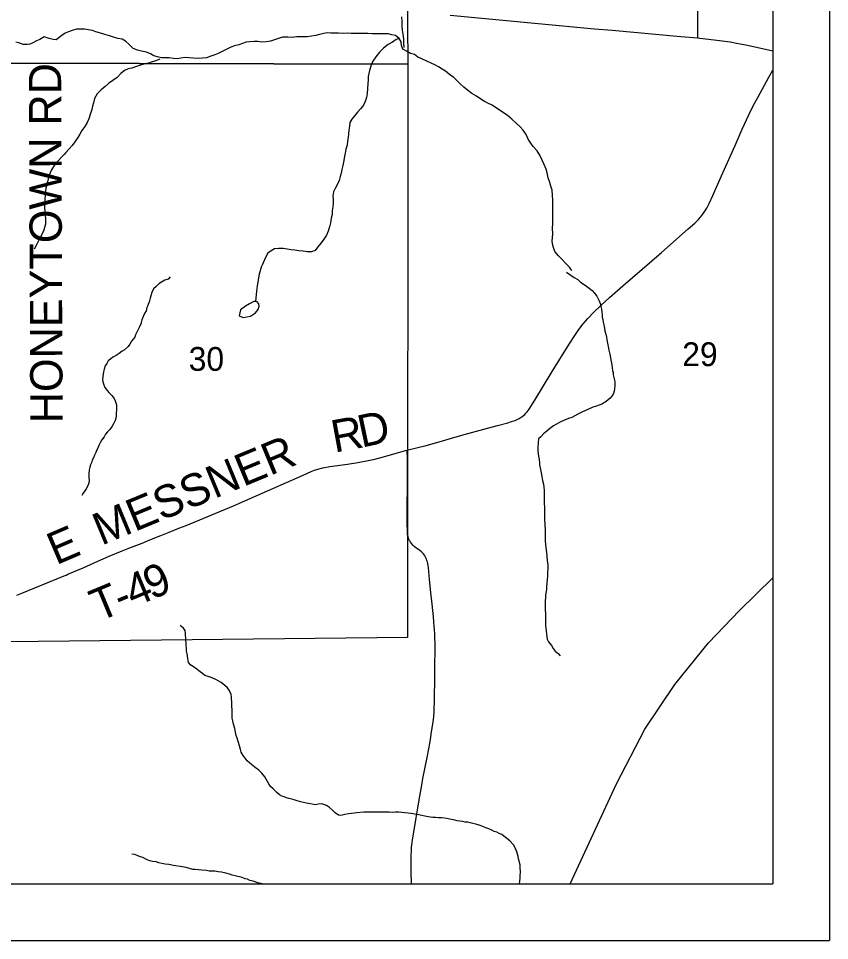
# Model space of a CAD drawing. Extents: x 0 to 34, y 0 to 22.
# Drawn here: x 23.331 to 24.758, y 9.078 to 10.698 of the extents above; entities that cross this region are included whole.
import ezdxf

# ---------------------------------------------------------------- set-up
doc = ezdxf.new("R2010")
doc.units = 0
for name, color, linetype in [('GM_X_County_Road_Text', 7, 'Continuous'), ('GM_X_Minor_Lake', 7, 'Continuous'), ('GM_X_Minor_River', 7, 'Continuous'), ('GM_X_Rail_Line', 7, 'Continuous'), ('GM_X_Section', 7, 'Continuous'), ('GM_X_Section_Text', 7, 'Continuous'), ('GM_X_Township_Road', 7, 'Continuous'), ('GM_X_Township_Road_Text', 7, 'Continuous'), ('GM_X_US_Route', 7, 'Continuous'), ('SH_Data', 7, 'Continuous')]:
    doc.layers.add(name, color=color, linetype=linetype)

msp = doc.modelspace()

# ---------------------------------------------------------------- linework, layer by layer
at = {"layer": 'GM_X_Minor_Lake'}
for points in [[(23.745, 10.2008), (23.7371, 10.197), (23.7303, 10.1927), (23.7216, 10.1862), (23.719, 10.1756), (23.7263, 10.173), (23.7391, 10.1753), (23.7478, 10.1807), (23.7526, 10.1868), (23.7545, 10.1925), (23.7537, 10.1967)], [(23.7537, 10.1967), (23.7511, 10.2002), (23.7491, 10.2011), (23.745, 10.2008)]]:
    msp.add_lwpolyline(points, dxfattribs=at)
at = {"layer": 'GM_X_Minor_River'}
for points in [[(24.0048, 10.7012), (24.0052, 10.6929), (24.0053, 10.6856), (24.0061, 10.678), (24.0073, 10.6708), (24.0085, 10.6628), (24.0086, 10.6552), (24.009, 10.6476)], [(23.407, 10.6682), (23.3973, 10.6611), (23.3917, 10.6615), (23.3852, 10.6633), (23.376, 10.6659), (23.3685, 10.6616), (23.3624, 10.6592), (23.356, 10.6557), (23.3507, 10.6534), (23.3462, 10.6526), (23.3389, 10.6525), (23.3313, 10.6554), (23.3263, 10.6565)], [(23.7109, 10.6505), (23.7045, 10.6478), (23.6976, 10.6447), (23.6905, 10.6409), (23.6825, 10.637), (23.6761, 10.6343), (23.6692, 10.6319), (23.6617, 10.6292), (23.6548, 10.6284), (23.6465, 10.6279), (23.6381, 10.6286), (23.6312, 10.6293), (23.6244, 10.6297), (23.6164, 10.6285), (23.61, 10.6276), (23.6039, 10.628), (23.5963, 10.6291), (23.5898, 10.6294), (23.5826, 10.6293), (23.5753, 10.6312), (23.5692, 10.633), (23.5631, 10.636), (23.5559, 10.639), (23.5475, 10.6408), (23.5406, 10.6427), (23.533, 10.6456), (23.5257, 10.6528), (23.5192, 10.6585), (23.5131, 10.6622), (23.5055, 10.6633), (23.4982, 10.6655), (23.491, 10.6677), (23.4826, 10.6703), (23.4735, 10.6729), (23.467, 10.6748), (23.4609, 10.677), (23.4472, 10.6799), (23.4399, 10.6799), (23.4331, 10.6794), (23.4255, 10.6775), (23.4191, 10.6751), (23.413, 10.6724), (23.407, 10.6682)], [(24.3044, 10.2554), (24.3001, 10.2614), (24.2929, 10.2686), (24.2875, 10.2746), (24.281, 10.2814), (24.2744, 10.2886), (24.2709, 10.2996), (24.2697, 10.3072), (24.2704, 10.3133), (24.2711, 10.3201), (24.2707, 10.33), (24.271, 10.3372), (24.2709, 10.3448), (24.2712, 10.352), (24.2711, 10.3627), (24.2711, 10.3692), (24.271, 10.3783), (24.2705, 10.3878), (24.2697, 10.3965), (24.2677, 10.4034), (24.2658, 10.4098), (24.2631, 10.4181), (24.2611, 10.4269), (24.2591, 10.4337), (24.2552, 10.4428), (24.2518, 10.4508), (24.2479, 10.4583), (24.2433, 10.4655), (24.2367, 10.4731), (24.2321, 10.4795), (24.2279, 10.4863), (24.224, 10.4946), (24.219, 10.5022), (24.2136, 10.5082), (24.2067, 10.5146), (24.1991, 10.5214), (24.1906, 10.5286), (24.1845, 10.5327), (24.1784, 10.5365), (24.1704, 10.5417), (24.1643, 10.5462), (24.1581, 10.5492), (24.1509, 10.5526), (24.1444, 10.5567), (24.1367, 10.5616), (24.1283, 10.5665), (24.1211, 10.5725), (24.1142, 10.5774), (24.108, 10.5838), (24.1019, 10.5895), (24.0965, 10.5955), (24.0897, 10.5996), (24.0824, 10.6057), (24.0763, 10.6094), (24.0698, 10.6135), (24.0637, 10.6169), (24.0568, 10.6199), (24.0492, 10.6236), (24.0408, 10.6274), (24.0335, 10.6304), (24.0274, 10.6349), (24.0205, 10.6367), (24.0133, 10.6408), (24.0071, 10.6446), (24.0048, 10.651), (24.004, 10.6571), (24.0009, 10.6632), (23.9944, 10.6684), (23.9875, 10.6695), (23.9814, 10.6714), (23.9746, 10.6717), (23.9533, 10.6715), (23.9453, 10.6718), (23.9362, 10.6721), (23.916, 10.672), (23.9092, 10.6723), (23.9024, 10.6722), (23.894, 10.6726), (23.8868, 10.6725), (23.8807, 10.6728), (23.8742, 10.6732), (23.8681, 10.672), (23.8605, 10.6704), (23.8541, 10.6684), (23.8465, 10.6672), (23.8389, 10.6664), (23.829, 10.6663), (23.8207, 10.6659), (23.8127, 10.6647), (23.8047, 10.6654), (23.7952, 10.6657), (23.7831, 10.6614), (23.7743, 10.6587), (23.7667, 10.6574), (23.7591, 10.657), (23.7519, 10.6577), (23.7454, 10.658), (23.7375, 10.6576), (23.7314, 10.6568), (23.7189, 10.6521), (23.7109, 10.6505)], [(24.0009, 10.6632), (23.9956, 10.6616), (23.9888, 10.657), (23.9816, 10.6527), (23.9733, 10.6462), (23.9661, 10.6393), (23.9594, 10.6309), (23.9545, 10.6232), (23.9508, 10.6145), (23.9482, 10.6072), (23.9463, 10.5966), (23.946, 10.5905), (23.9457, 10.584), (23.945, 10.5756), (23.9443, 10.5665), (23.9432, 10.5596), (23.9406, 10.5524), (23.938, 10.5463), (23.9331, 10.5402), (23.9275, 10.5337), (23.9177, 10.5214), (23.914, 10.5153), (23.9132, 10.5092), (23.9122, 10.502), (23.9115, 10.4955), (23.9108, 10.4894), (23.9097, 10.4829), (23.909, 10.4757), (23.9071, 10.4685), (23.9057, 10.4616), (23.9046, 10.4555), (23.9028, 10.446), (23.9017, 10.4399), (23.8998, 10.433), (23.8984, 10.4266), (23.8969, 10.4205), (23.895, 10.4136), (23.8921, 10.4071), (23.8887, 10.4006), (23.8853, 10.3934), (23.8842, 10.3865), (23.8847, 10.3804), (23.8844, 10.3732), (23.8837, 10.3671), (23.8826, 10.3603), (23.8826, 10.3538), (23.8808, 10.3473), (23.8797, 10.339), (23.8779, 10.3321), (23.876, 10.3245), (23.8727, 10.3176), (23.8682, 10.3103), (23.8633, 10.3042), (23.8576, 10.2969), (23.8527, 10.2904), (23.8467, 10.2881), (23.8391, 10.2884), (23.8315, 10.2895), (23.8239, 10.2898), (23.817, 10.2909), (23.8105, 10.292), (23.8037, 10.2927), (23.7964, 10.2938), (23.7885, 10.2941), (23.7816, 10.2933), (23.7756, 10.2902), (23.7695, 10.286), (23.7662, 10.2795), (23.7589, 10.2635)], [(23.5795, 10.627), (23.5723, 10.6239), (23.5659, 10.622), (23.5598, 10.62), (23.5538, 10.6184), (23.5454, 10.6165), (23.5386, 10.6138), (23.5303, 10.611), (23.5238, 10.6098), (23.5174, 10.6067), (23.5109, 10.6014), (23.5045, 10.5948), (23.497, 10.5891), (23.4894, 10.5844), (23.4834, 10.5791), (23.4762, 10.5729), (23.4694, 10.5657), (23.4646, 10.5576), (23.4631, 10.5504), (23.4609, 10.5443), (23.4602, 10.5382), (23.4572, 10.5298), (23.4546, 10.5222), (23.452, 10.5157), (23.4475, 10.5084), (23.4422, 10.5012), (23.4388, 10.4951), (23.4351, 10.4889), (23.4298, 10.4813), (23.4253, 10.4752), (23.4201, 10.469), (23.414, 10.4629), (23.4115, 10.4595)], [(23.4119, 10.46), (23.3957, 10.4428), (23.3893, 10.4321), (23.3845, 10.4217), (23.382, 10.4111), (23.3791, 10.4), (23.3781, 10.3901), (23.3771, 10.3787), (23.3765, 10.3662), (23.3783, 10.3464), (23.3784, 10.3366), (23.3751, 10.3247), (23.3692, 10.3133), (23.3636, 10.3029), (23.3588, 10.293)], [(23.7487, 10.2011), (23.7501, 10.2191), (23.7512, 10.2286), (23.7534, 10.2384), (23.7552, 10.2498), (23.7589, 10.2635)], [(24.2951, 10.2523), (24.3008, 10.2481), (24.3084, 10.2432), (24.3149, 10.2398), (24.3198, 10.2349), (24.3278, 10.2296), (24.335, 10.2244), (24.34, 10.2202), (24.3446, 10.2153), (24.3484, 10.21), (24.3522, 10.2032), (24.3549, 10.1963), (24.3557, 10.1922), (24.3569, 10.1876), (24.3573, 10.1823), (24.3577, 10.1773), (24.3581, 10.1735), (24.3589, 10.1694), (24.3593, 10.1644), (24.3605, 10.1599), (24.3612, 10.1572)], [(23.5978, 10.244), (23.594, 10.2401), (23.5887, 10.2382), (23.5827, 10.2351), (23.5778, 10.2317), (23.5733, 10.2275), (23.5684, 10.2229), (23.5658, 10.2168), (23.564, 10.2107), (23.5625, 10.2065), (23.5614, 10.202), (23.5584, 10.194), (23.5565, 10.1901), (23.5555, 10.1844), (23.5525, 10.1799), (23.551, 10.1757), (23.548, 10.1688), (23.5469, 10.1642)], [(23.5469, 10.1642), (23.5465, 10.1627), (23.5439, 10.1566), (23.5402, 10.1494), (23.5368, 10.1421), (23.5354, 10.1383), (23.5297, 10.1311), (23.5267, 10.1257), (23.5237, 10.1219), (23.5173, 10.1162), (23.5136, 10.1135), (23.5079, 10.1097), (23.5027, 10.1062), (23.497, 10.1028), (23.4929, 10.0997), (23.4887, 10.0966), (23.4861, 10.0921), (23.4835, 10.0879), (23.4816, 10.0818), (23.4805, 10.0772), (23.4798, 10.0734), (23.4791, 10.0688), (23.4788, 10.0635), (23.4792, 10.0597), (23.4811, 10.0544), (23.483, 10.0495), (23.4868, 10.0445), (23.4899, 10.0408), (23.4952, 10.0359), (23.4994, 10.0302), (23.5013, 10.0264), (23.5033, 10.0195), (23.5034, 10.0097), (23.503, 10.0051), (23.503, 10.0002), (23.5023, 9.996), (23.5012, 9.9918), (23.4982, 9.9857), (23.4956, 9.9819), (23.4919, 9.9761), (23.4877, 9.9719), (23.484, 9.9674), (23.4817, 9.9628), (23.4776, 9.9578), (23.4754, 9.9536), (23.4728, 9.9491), (23.4691, 9.941)], [(24.3612, 10.1572), (24.362, 10.1542), (24.3628, 10.1485), (24.364, 10.1435), (24.3652, 10.1382), (24.3663, 10.1333), (24.3671, 10.1276), (24.3683, 10.1219), (24.3695, 10.1151), (24.3711, 10.1082), (24.3726, 10.1021), (24.3738, 10.0953), (24.3746, 10.0896), (24.3754, 10.0843), (24.3762, 10.0797), (24.377, 10.0759), (24.3774, 10.0718), (24.3793, 10.0626), (24.3801, 10.0589), (24.3802, 10.0531), (24.3795, 10.0471), (24.3791, 10.0433), (24.3776, 10.0391), (24.3746, 10.0345), (24.372, 10.0307), (24.3649, 10.0253), (24.3573, 10.0203), (24.3528, 10.0184), (24.346, 10.0165), (24.3415, 10.0149), (24.3324, 10.0111), (24.3286, 10.0092), (24.3222, 10.0065), (24.3151, 10.0026), (24.3045, 9.9972), (24.3004, 9.9957), (24.2958, 9.9938), (24.2864, 9.9899), (24.2826, 9.988), (24.2762, 9.9849), (24.2721, 9.9822), (24.2653, 9.9773), (24.2604, 9.9727), (24.2548, 9.9681), (24.2499, 9.9631), (24.2461, 9.9597), (24.245, 9.9524), (24.2447, 9.9441), (24.2448, 9.9376), (24.2456, 9.9289), (24.2468, 9.9232), (24.2476, 9.9175), (24.2476, 9.9137), (24.2492, 9.9053), (24.2503, 9.9), (24.2515, 9.8932), (24.2531, 9.886), (24.2546, 9.8799), (24.2554, 9.8746), (24.2559, 9.8689), (24.2559, 9.8635), (24.2556, 9.8586), (24.256, 9.854), (24.2556, 9.8495), (24.2557, 9.8449), (24.2561, 9.8404), (24.2561, 9.8293), (24.2562, 9.8229), (24.2566, 9.8164), (24.2567, 9.8103), (24.2571, 9.8058), (24.2575, 9.802), (24.2576, 9.7807), (24.2584, 9.7731), (24.2593, 9.7643), (24.2605, 9.7537), (24.2613, 9.745), (24.2621, 9.7385), (24.2625, 9.7313), (24.2618, 9.7244), (24.2615, 9.7195), (24.2608, 9.7111)], [(23.4691, 9.941), (23.4683, 9.9391), (23.4668, 9.9353), (23.4646, 9.9308), (23.4627, 9.9262), (23.4608, 9.922), (23.4594, 9.9174), (23.4575, 9.9136), (23.4564, 9.9098), (23.4553, 9.9052), (23.4546, 9.8976), (23.455, 9.8931), (23.4551, 9.8843), (23.4543, 9.8801), (23.4525, 9.8756), (23.4502, 9.8718), (23.4476, 9.8679), (23.445, 9.8638), (23.4424, 9.8599)], [(24.2608, 9.7111), (24.2604, 9.7066), (24.2597, 9.699), (24.2598, 9.6948), (24.2594, 9.691), (24.2583, 9.6849), (24.2583, 9.6811), (24.2576, 9.6735), (24.2573, 9.6685), (24.2577, 9.6632), (24.2577, 9.659), (24.2582, 9.6526), (24.2582, 9.6461), (24.2579, 9.6419), (24.2579, 9.6358), (24.2579, 9.6313), (24.2587, 9.6267), (24.2604, 9.6115), (24.2611, 9.6074), (24.2634, 9.6028), (24.2684, 9.596), (24.2715, 9.5907), (24.2753, 9.5865), (24.2802, 9.582), (24.2837, 9.5782)], [(23.7129, 9.4436), (23.7113, 9.4504), (23.7094, 9.4577), (23.7078, 9.4637), (23.707, 9.4687), (23.7066, 9.4751), (23.7064, 9.4976), (23.706, 9.5017), (23.7056, 9.5055), (23.7052, 9.5101), (23.7018, 9.5177), (23.6987, 9.5215), (23.6941, 9.526), (23.6877, 9.5313), (23.682, 9.5343), (23.6782, 9.5362), (23.6698, 9.5399), (23.6645, 9.5418), (23.6588, 9.5437), (23.6546, 9.5467), (23.6508, 9.5501), (23.6421, 9.5565), (23.6341, 9.5614), (23.6303, 9.5663), (23.6291, 9.5735), (23.6283, 9.5777), (23.6275, 9.5815), (23.6267, 9.5861), (23.6263, 9.5903), (23.6259, 9.5971), (23.6259, 9.6009), (23.6255, 9.6051), (23.6254, 9.6093), (23.625, 9.6142), (23.6246, 9.618), (23.6242, 9.6226), (23.6211, 9.6267), (23.6154, 9.6316)], [(24.2141, 9.1984), (24.2137, 9.206), (24.2133, 9.2106), (24.2109, 9.2212), (24.2098, 9.2254), (24.2086, 9.2292), (24.2078, 9.2334), (24.2055, 9.2395), (24.2021, 9.2455), (24.1956, 9.2527), (24.1849, 9.261), (24.1811, 9.2637), (24.1769, 9.2655), (24.1724, 9.2678), (24.1678, 9.2693), (24.1637, 9.2715), (24.1587, 9.2738), (24.1534, 9.2757), (24.1477, 9.2779), (24.1417, 9.2802), (24.1356, 9.282), (24.1303, 9.2835), (24.1257, 9.2846), (24.1212, 9.2854), (24.117, 9.2857), (24.1125, 9.2869), (24.1075, 9.2872), (24.103, 9.2879), (24.0985, 9.2891), (24.0928, 9.2902), (24.0867, 9.2913), (24.0806, 9.2924), (24.0753, 9.2931), (24.0697, 9.2935), (24.0647, 9.2938), (24.0602, 9.2938), (24.056, 9.2945), (24.0515, 9.2953), (24.0458, 9.296), (24.0405, 9.2975), (24.0348, 9.2986), (24.0219, 9.3008), (24.0163, 9.3012), (24.0109, 9.3019), (24.0053, 9.3026), (24, 9.303), (23.9943, 9.3033), (23.9882, 9.3029), (23.9829, 9.3033), (23.9644, 9.3032), (23.9599, 9.3035), (23.9527, 9.3035), (23.9462, 9.3031), (23.9383, 9.303), (23.9262, 9.3018), (23.9171, 9.301), (23.9114, 9.3002), (23.905, 9.299), (23.8978, 9.2975), (23.8937, 9.2982), (23.8883, 9.302), (23.8842, 9.3062), (23.8784, 9.3114), (23.8727, 9.3148), (23.8682, 9.3167), (23.8644, 9.3178), (23.858, 9.317), (23.8534, 9.3163), (23.8413, 9.3185), (23.8375, 9.3192), (23.8269, 9.3211), (23.8197, 9.3237), (23.8159, 9.3248), (23.8117, 9.3259), (23.8068, 9.3274), (23.8026, 9.3285), (23.7981, 9.33), (23.7943, 9.3311), (23.7901, 9.3334), (23.7852, 9.3376), (23.7791, 9.344), (23.7745, 9.3485), (23.7711, 9.3531), (23.7688, 9.3572), (23.7665, 9.361), (23.7642, 9.3656), (23.7592, 9.372), (23.7539, 9.3769), (23.7474, 9.3818), (23.7417, 9.3864), (23.7375, 9.3898), (23.7333, 9.3935), (23.7295, 9.3981), (23.7261, 9.4026), (23.723, 9.4087), (23.7214, 9.4136), (23.7199, 9.4201), (23.7175, 9.4273), (23.7156, 9.4334), (23.7141, 9.4379), (23.7129, 9.4436)], [(23.7595, 9.1775), (23.7523, 9.1792), (23.7439, 9.1819), (23.7382, 9.1833), (23.7337, 9.1852), (23.7295, 9.1863), (23.7246, 9.1882), (23.7124, 9.1912), (23.7071, 9.1927), (23.7022, 9.1942), (23.6958, 9.196), (23.6882, 9.1975), (23.6821, 9.1986), (23.6764, 9.1994), (23.6666, 9.1997), (23.662, 9.2004), (23.6533, 9.2011), (23.6416, 9.2026), (23.6374, 9.2026), (23.6261, 9.2059), (23.6154, 9.2078), (23.6079, 9.2089), (23.6037, 9.2096), (23.5954, 9.2115), (23.5889, 9.2118), (23.5829, 9.2129), (23.5779, 9.214), (23.573, 9.2159), (23.5666, 9.2166), (23.562, 9.2174), (23.5563, 9.22), (23.5495, 9.2234), (23.5457, 9.2249), (23.5411, 9.2264), (23.5358, 9.2286), (23.5305, 9.2294)], [(24.2124, 9.1775), (24.2131, 9.1821), (24.2135, 9.187), (24.2138, 9.1912), (24.2141, 9.1984)]]:
    msp.add_lwpolyline(points, dxfattribs=at)
at = {"layer": 'GM_X_Rail_Line'}
msp.add_lwpolyline([(24.3018, 9.1775), (24.3833, 9.3528), (24.4329, 9.4492), (24.4857, 9.5274), (24.5448, 9.6007), (24.5992, 9.6577), (24.6579, 9.7151)], dxfattribs=at)
at = {"layer": 'GM_X_Section'}
for points in [[(23.2983, 11.6235), (24.0077, 11.623), (24.0161, 10.618), (23.3079, 10.6196)], [(23.3079, 10.6196), (24.0161, 10.618), (24.0154, 9.6102), (23.3119, 9.6024)]]:
    msp.add_lwpolyline(points, close=True, dxfattribs=at)
at = {"layer": 'GM_X_Township_Road'}
for points in [[(24.5261, 10.6641), (24.5261, 10.6692), (24.5263, 10.6899), (24.5264, 10.7489)], [(24.0144, 9.9393), (24.048, 9.948), (24.0749, 9.9553), (24.0927, 9.9606), (24.1107, 9.9657), (24.1496, 9.9765), (24.1736, 9.983), (24.1917, 9.9876), (24.1986, 9.9898), (24.2026, 9.9912), (24.2045, 9.9919), (24.2083, 9.9936), (24.2117, 9.9954), (24.2169, 9.9986), (24.2194, 10.0005), (24.2216, 10.0024), (24.2238, 10.0046), (24.2257, 10.0069), (24.2293, 10.0119), (24.2392, 10.0277), (24.2701, 10.0781), (24.2995, 10.1257), (24.3097, 10.1414), (24.3169, 10.1516), (24.3246, 10.1614), (24.3327, 10.1709), (24.3434, 10.1822), (24.3547, 10.193), (24.3708, 10.2077), (24.3941, 10.2283), (24.4623, 10.2873), (24.509, 10.3284), (24.5206, 10.3387), (24.5272, 10.3452), (24.5332, 10.3522), (24.5386, 10.3597), (24.5419, 10.3649), (24.5462, 10.3731), (24.5528, 10.3871), (24.5704, 10.427), (24.5921, 10.4752), (24.6044, 10.5037), (24.6161, 10.5292), (24.6243, 10.546), (24.6316, 10.5597), (24.651, 10.5952), (24.6579, 10.6075)], [(23.3281, 9.6848), (23.3368, 9.688), (23.3598, 9.6973), (23.3855, 9.7083), (23.4113, 9.7187), (23.4146, 9.7201), (23.4175, 9.7213), (23.4446, 9.733), (23.4705, 9.7446), (23.4906, 9.7531), (23.5136, 9.7625), (23.5251, 9.7672), (23.5483, 9.7763), (23.5619, 9.7817), (23.5815, 9.7896), (23.5958, 9.7953), (23.6131, 9.8023), (23.6259, 9.8074), (23.7092, 9.8419), (23.7691, 9.868), (23.8118, 9.8867), (23.8315, 9.8958), (23.8457, 9.9022), (23.8515, 9.9044), (23.8575, 9.9063), (23.8666, 9.9085), (23.8789, 9.9106), (23.9096, 9.9149), (23.9279, 9.9179), (23.9461, 9.9212), (23.9581, 9.9239), (23.9731, 9.9279), (24.012, 9.9387), (24.0144, 9.9393)], [(24.0222, 9.1775), (24.0221, 9.1827), (24.022, 9.1935), (24.0219, 9.216), (24.0219, 9.2277), (24.0221, 9.2347), (24.0225, 9.2419), (24.0234, 9.25), (24.0241, 9.2546), (24.0265, 9.2683), (24.0306, 9.293), (24.0336, 9.3107), (24.0371, 9.3311), (24.0404, 9.3505), (24.0426, 9.3622), (24.0498, 9.3991), (24.0527, 9.4145), (24.0558, 9.4312), (24.0578, 9.4443), (24.0594, 9.4543), (24.0605, 9.4619), (24.0614, 9.4708), (24.062, 9.4793), (24.0623, 9.4847), (24.0624, 9.4881), (24.0626, 9.4946), (24.0629, 9.511), (24.0633, 9.5298), (24.0636, 9.555), (24.064, 9.594), (24.0633, 9.6157), (24.0628, 9.6247), (24.0625, 9.6302), (24.0619, 9.6373), (24.061, 9.6472), (24.0598, 9.6577), (24.0585, 9.669), (24.0562, 9.6896), (24.0541, 9.7121), (24.0527, 9.7265), (24.0521, 9.7331), (24.0515, 9.7369), (24.0511, 9.7395), (24.0503, 9.7432), (24.0495, 9.7459), (24.0488, 9.7481), (24.0478, 9.7504), (24.0466, 9.7528), (24.0451, 9.7551), (24.0433, 9.7575), (24.0418, 9.7591), (24.0398, 9.7609), (24.0368, 9.7632), (24.0296, 9.7682), (24.0272, 9.7704), (24.0246, 9.7728), (24.0229, 9.7748), (24.0206, 9.7777), (24.0193, 9.7799), (24.0185, 9.7814), (24.0176, 9.7832), (24.0169, 9.7856), (24.0163, 9.7876), (24.0156, 9.7916), (24.0154, 9.795), (24.0151, 9.8009), (24.015, 9.8067), (24.0155, 9.9096), (24.0154, 9.9193), (24.0153, 9.925), (24.0152, 9.9298), (24.0149, 9.9336), (24.0146, 9.9369), (24.0144, 9.9393)]]:
    msp.add_lwpolyline(points, dxfattribs=at)
at = {"layer": 'GM_X_US_Route'}
msp.add_lwpolyline([(24.0907, 10.704), (24.2455, 10.6898), (24.3446, 10.6805), (24.3757, 10.6777), (24.4963, 10.6668), (24.5261, 10.6641), (24.5294, 10.6638), (24.5551, 10.6611), (24.5739, 10.6587), (24.5829, 10.6573), (24.5939, 10.6553), (24.6104, 10.652), (24.6504, 10.6431), (24.6579, 10.6416)], dxfattribs=at)
at = {"layer": 'SH_Data'}
for p, q in [((24.7579, 16.0775), (24.7579, 9.0775)), ((24.6579, 15.9775), (24.6579, 9.1775)), ((17.8579, 9.1775), (24.6579, 9.1775)), ((17.7579, 9.0775), (24.7579, 9.0775))]:
    msp.add_line(p, q, dxfattribs=at)

# ---------------------------------------------------------------- texts
at = {"layer": 'GM_X_County_Road_Text'}
msp.add_text('HONEYTOWN RD', height=0.056818, rotation=90.2529, dxfattribs=at).set_placement((23.4087, 9.987))
at = {"layer": 'GM_X_Section_Text'}
for s, p in [('30', (23.6304, 10.079)), ('29', (24.4987, 10.0873))]:
    msp.add_text(s, height=0.04186, rotation=0, dxfattribs=at).set_placement(p)
at = {"layer": 'GM_X_Township_Road_Text'}
for s, height, rotation, p in [('D', 0.0568, 11.9593, (23.9344, 9.9438)), ('R', 0.0568, 10.3446, (23.8868, 9.9351)), ('MESSNER', 0.05682, 22.507, (23.4768, 9.7714)), ('E', 0.0568, 23.1938, (23.3971, 9.737)), ('4', 0.0568, 22.5845, (23.5328, 9.6627)), ('9', 0.0568, 22.731, (23.5653, 9.6762)), ('T', 0.0568, 22.5447, (23.472, 9.6374)), ('-', 0.0568, 22.5535, (23.5113, 9.6537))]:
    msp.add_text(s, height=height, rotation=rotation, dxfattribs=at).set_placement(p)

doc.saveas('drawing.dxf')
